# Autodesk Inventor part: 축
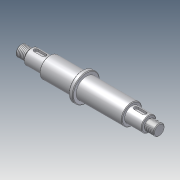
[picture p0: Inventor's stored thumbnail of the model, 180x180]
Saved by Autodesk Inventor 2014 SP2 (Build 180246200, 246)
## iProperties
Company: 한국ATC센터
Created: 2015-02
Part Number: 축
Document SubType Name: Modeling
Designer: KYOUNG IL JANG
Density: 1 g/cm^3
Material: 일반
Appearance: 기본값
Author: KYOUNG IL JANG
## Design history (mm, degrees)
sketch "스케치1"
  geometry: L1 (0, 0)-(203, 0); L2 (203, 0)-(203, 8); L3 (203, 8)-(189.5, 8); L4 (189.5, 8)-(189.5, 7); L5 (189.5, 7)-(188, 7); L6 (188, 7)-(188, 11); L7 (188, 11)-(163, 11); L8 (163, 11)-(163, 15); L9 (163, 15)-(96, 15); L10 (96, 15)-(96, 20); L11 (96, 20)-(90, 20); L12 (90, 20)-(90, 15); L13 (90, 15)-(42, 15); L14 (42, 15)-(42, 11); L15 (42, 11)-(15, 11); L16 (15, 11)-(15, 7); L17 (15, 7)-(13.5, 7); L18 (0, 8)-(0, 0); L19 (0, 8)-(13.5, 8); L20 (13.5, 8)-(13.5, 7)
  constraints: 40 end point, 16 parallel, 3 perpendicular, 1 collinear, 1 horizontal
  dimensions: "d0" = 16 diameter of L3 L1; "d1" = 14 diameter of L5 L1; "d2" = 22 diameter of L7 L1; "d3" = 30 diameter of L9 L1; "d4" = 40 diameter of L11 L1; "d5" = 16 diameter of L19 L1; "d6" = 22 diameter of L15 L1; "d8" = 1.5 distance of L16.end L17.end; "d9" = 15 distance between parallel lines of L16 L18; "d10" = 27 distance between parallel lines of L14 L16; "d11" = 48 distance between parallel lines of L12 L14; "d15" = 203 distance of L1.start L1.end; "d16" = 1.5 distance of L4.end L5.end; "d17" = 14 diameter of L17 L1; "d36" = 15 distance between parallel lines of L6 L2; "d37" = 25 distance between parallel lines of L6 L8; "d38" = 6 distance between parallel lines of L10 L12
revolve "회전1" sketch "스케치1" stored, may be unused: angle "d18" = 90 deg
feature "스레드1" dims "d19" = 10, "d20" = 0
feature "스레드2" dims "d21" = 10, "d22" = 0
chamfer "모따기1" distance "d23" = 1; stored, may be unused: second distance "d24" = 2, angle "d25" = 45 deg
node "작업 평면1"
sketch "스케치2"
  geometry: L1 (-6.5, 3)-(5.5, 3); L2 (5.5, -3)-(-6.5, -3); L3 (-13.5, -10)-(-13.5, 10) reference; L4 (140.5, 3)-(152.5, 3); L5 (152.5, -3)-(140.5, -3); L6 (159.5, 10)-(159.5, -10) reference; A1 r 3 centre (5.5, 0) between (5.5, -3) and (5.5, 3); A2 r 3 centre (-6.5, 0) between (-6.5, 3) and (-6.5, -3); A3 r 3 centre (152.5, 0) between (152.5, -3) and (152.5, 3); A4 r 3 centre (140.5, 0) between (140.5, 3) and (140.5, -3); 1 further point
  constraints: 8 end point, 8 point on circle, 8 tangent, 4 centre point, 2 horizontal, 2 horizontal alignment, 2 parallel
  dimensions: "d26" = 6 distance between parallel lines of L2 L1; "d27" = 18 dimension on A1 A2; "d28" = 4 distance edge to line of A2 L3; "d29" = 6 distance between parallel lines of L5 L4; "d30" = 18 dimension on A3 A4; "d31" = 4 distance edge to line of A3 L6
extrude "돌출1" cut sketch "스케치2" distance "d32" = 3.5; taper "d33" = 0 deg
node "솔리드1"
